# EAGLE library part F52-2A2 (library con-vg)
CONNECTOR female, 52 pins + 2 high current, type C
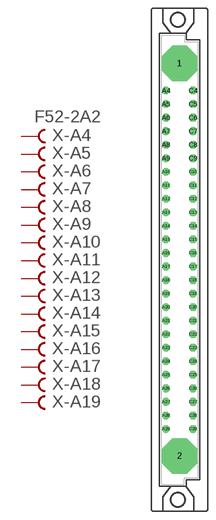
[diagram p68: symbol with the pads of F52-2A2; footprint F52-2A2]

Designator prefix X; gates -A4=FVAL -A5=FEM -A6=FEM -A7=FEM -A8=FEM -A9=FEM -A10=FEM -A11=FEM -A12=FEM -A13=FEM -A14=FEM -A15=FEM -A16=FEM -A17=FEM -A18=FEM -A19=FEM -A20=FEM -A21=FEM -A22=FEM -A23=FEM -A24=FEM -A25=FEM -A26=FEM -A27=FEM -A28=FEM -A29=FEM -C4=FVAL -C5=FEM -C6=FEM -C7=FEM -C8=FEM -C9=FEM -C10=FEM -C11=FEM -C12=FEM -C13=FEM -C14=FEM -C15=FEM -C16=FEM -C17=FEM -C18=FEM -C19=FEM -C20=FEM -C21=FEM -C22=FEM -C23=FEM -C24=FEM -C25=FEM -C26=FEM -C27=FEM -C28=FEM -C29=FEM -1=FEM-HIGHCUR -2=FEM-HIGHCUR

## F52-2A2  [F52-2A2]
1  -1:B  pas
2  -2:B  pas
A4  -A4:B  pas
A5  -A5:B  pas
A6  -A6:B  pas
A7  -A7:B  pas
A8  -A8:B  pas
A9  -A9:B  pas
A10  -A10:B  pas
A11  -A11:B  pas
A12  -A12:B  pas
A13  -A13:B  pas
A14  -A14:B  pas
A15  -A15:B  pas
A16  -A16:B  pas
A17  -A17:B  pas
A18  -A18:B  pas
A19  -A19:B  pas
A20  -A20:B  pas
A21  -A21:B  pas
A22  -A22:B  pas
A23  -A23:B  pas
A24  -A24:B  pas
A25  -A25:B  pas
A26  -A26:B  pas
A27  -A27:B  pas
A28  -A28:B  pas
A29  -A29:B  pas
C4  -C4:B  pas
C5  -C5:B  pas
C6  -C6:B  pas
C7  -C7:B  pas
C8  -C8:B  pas
C9  -C9:B  pas
C10  -C10:B  pas
C11  -C11:B  pas
C12  -C12:B  pas
C13  -C13:B  pas
C14  -C14:B  pas
C15  -C15:B  pas
C16  -C16:B  pas
C17  -C17:B  pas
C18  -C18:B  pas
C19  -C19:B  pas
C20  -C20:B  pas
C21  -C21:B  pas
C22  -C22:B  pas
C23  -C23:B  pas
C24  -C24:B  pas
C25  -C25:B  pas
C26  -C26:B  pas
C27  -C27:B  pas
C28  -C28:B  pas
C29  -C29:B  pas

## Footprint F52-2A2 (pad centres in mm)
CONNECTOR female, 52 pins + 2 high current, type C
drill 5.7 octagon: 1 0,36.83; 2 0,-36.83
drill 0.914 octagon: A4 -2.54,31.75; A5 -2.54,29.21; A6 -2.54,26.67; A7 -2.54,24.13; A8 -2.54,21.59; A9 -2.54,19.05; A10 -2.54,16.51; A11 -2.54,13.97; A12 -2.54,11.43; A13 -2.54,8.89; A14 -2.54,6.35; A15 -2.54,3.81; A16 -2.54,1.27; A17 -2.54,-1.27; A18 -2.54,-3.81; A19 -2.54,-6.35; A20 -2.54,-8.89; A21 -2.54,-11.43; A22 -2.54,-13.97; A23 -2.54,-16.51; A24 -2.54,-19.05; A25 -2.54,-21.59; A26 -2.54,-24.13; A27 -2.54,-26.67; A28 -2.54,-29.21; A29 -2.54,-31.75; C4 2.54,31.75; C5 2.54,29.21; C6 2.54,26.67; C7 2.54,24.13; C8 2.54,21.59; C9 2.54,19.05; C10 2.54,16.51; C11 2.54,13.97; C12 2.54,11.43; C13 2.54,8.89; C14 2.54,6.35; C15 2.54,3.81; C16 2.54,1.27; C17 2.54,-1.27; C18 2.54,-3.81; C19 2.54,-6.35; C20 2.54,-8.89; C21 2.54,-11.43; C22 2.54,-13.97; C23 2.54,-16.51; C24 2.54,-19.05; C25 2.54,-21.59; C26 2.54,-24.13; C27 2.54,-26.67; C28 2.54,-29.21; C29 2.54,-31.75
hole 2.794 at -0.305,45.009
hole 2.794 at -0.305,-45.009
